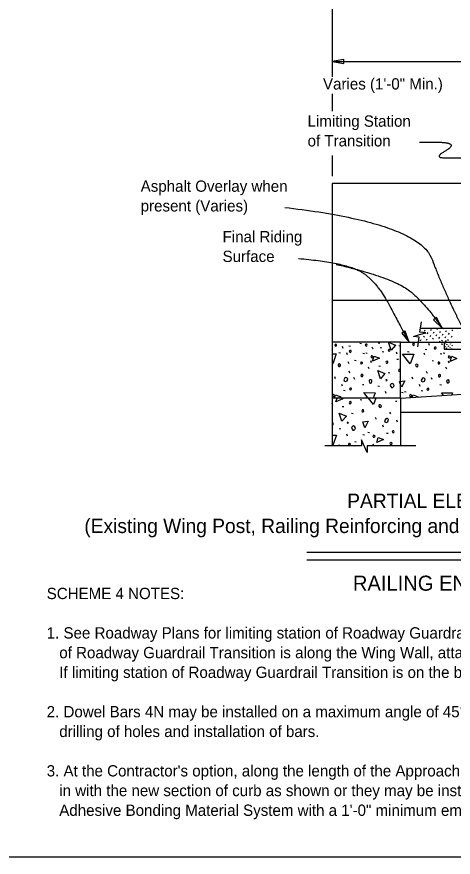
# Model space of a CAD drawing. Extents: x 1.5 to 68.7, y 0 to 31.1.
# Drawn here: x 20.65 to 28.44, y 1.78 to 16.79 of the extents above; entities that cross this region are included whole.
import ezdxf

# ---------------------------------------------------------------- set-up
doc = ezdxf.new("R2010")
doc.units = 0
for name, color, linetype in [('ActivePts-ConstElements', 7, 'Continuous'), ('AdhocPoint_dp', 7, 'Continuous'), ('Patterning', 7, 'Continuous'), ('PlotBorder_dp', 7, 'Continuous'), ('SheetBorder_dp', 7, 'Continuous')]:
    doc.layers.add(name, color=color, linetype=linetype)

msp = doc.modelspace()

# ---------------------------------------------------------------- linework, layer by layer
at = {"layer": 'ActivePts-ConstElements'}
msp.add_lwpolyline([(1.467, 28.183), (42.533, 28.183), (42.533, 1.783), (1.467, 1.783)], close=True, dxfattribs=at)
at = {"layer": 'AdhocPoint_dp'}
for p, q in [((26.277, 20.091), (26.277, 15.724)), ((26.277, 15.416), (26.277, 15.106)), ((26.277, 14.316), (26.277, 13.949)), ((30.085, 7.224), (25.826, 7.224)), ((30.085, 7.091), (25.826, 7.091))]:
    msp.add_line(p, q, dxfattribs=at)
for points in [[(26.277, 15.998), (26.485, 15.963), (26.485, 16.033)], [(28.238, 11.235), (28.141, 11.423), (28.085, 11.381)], [(27.652, 10.983), (27.579, 11.181), (27.518, 11.146)]]:
    msp.add_lwpolyline(points, close=True, dxfattribs=at)
for points in [[(26.277, 15.998), (29.811, 15.998)], [(27.809, 10.898), (27.832, 11.072), (27.73, 11.086), (27.838, 11.117), (27.947, 11.148), (27.844, 11.161), (27.869, 11.344)], [(27.77, 9.13), (26.901, 9.13), (26.901, 9.013), (26.802, 9.238), (26.802, 9.13), (26.146, 9.13)]]:
    msp.add_lwpolyline(points, dxfattribs=at)
for points in [[(27.836, 14.553), (28.073, 14.553), (28.329, 14.553), (28.447, 14.486), (28.102, 14.277), (28.44, 14.277), (28.701, 14.277)], [(25.434, 13.39), (27.814, 13.112), (28.299, 11.826), (28.608, 11.234)], [(25.677, 12.477), (26.504, 12.407), (27.069, 12.08), (27.575, 11.117), (27.652, 10.983)], [(26.348, 12.372), (27.415, 12.129), (28.009, 11.586), (28.238, 11.235)]]:
    msp.add_open_spline(points, degree=2, dxfattribs=at)
at = {"layer": 'Patterning'}
for p, q in [((27.878, 11.229), (27.881, 11.234)), ((27.927, 11.18), (27.94, 11.202)), ((27.975, 11.131), (27.988, 11.154)), ((28.037, 11.193), (28.05, 11.215)), ((28.086, 11.144), (28.099, 11.167)), ((28.135, 11.095), (28.148, 11.118)), ((28.148, 11.206), (28.161, 11.228)), ((28.197, 11.157), (28.21, 11.18)), ((28.245, 11.108), (28.258, 11.131)), ((28.258, 11.219), (28.267, 11.234)), ((28.307, 11.17), (28.32, 11.193)), ((28.356, 11.121), (28.369, 11.144)), ((28.369, 11.232), (28.371, 11.234)), ((28.418, 11.183), (28.431, 11.205)), ((26.77, 10.962), (26.8, 10.957)), ((27.099, 10.97), (27.129, 10.965)), ((27.812, 10.988), (27.825, 11.01)), ((27.852, 11.008), (27.865, 11.03)), ((27.914, 11.069), (27.927, 11.092)), ((27.962, 11.021), (27.975, 11.043)), ((28.024, 11.082), (28.037, 11.105)), ((28.073, 11.034), (28.086, 11.056)), ((28.184, 11.047), (28.197, 11.069)), ((28.194, 10.982), (28.205, 11)), ((28.233, 10.998), (28.245, 11.02)), ((28.294, 11.059), (28.307, 11.082)), ((28.298, 10.964), (28.306, 10.978)), ((28.303, 10.991), (28.316, 11.013)), ((28.343, 11.011), (28.356, 11.033)), ((28.361, 10.972), (28.368, 10.984)), ((28.399, 10.983), (28.4, 10.984)), ((28.405, 11.072), (28.418, 11.095)), ((28.425, 10.98), (28.427, 10.984)), ((26.474, 10.868), (26.46, 10.904)), ((26.574, 10.918), (26.604, 10.912)), ((27.007, 10.856), (26.993, 10.892)), ((27.135, 10.886), (27.165, 10.88)), ((27.171, 10.814), (27.201, 10.808)), ((27.467, 10.926), (27.497, 10.92)), ((27.619, 10.814), (27.649, 10.808)), ((27.94, 10.858), (27.97, 10.852)), ((28.016, 10.921), (28.002, 10.956)), ((28.224, 10.954), (28.254, 10.949)), ((28.289, 10.9), (28.298, 10.914)), ((28.317, 10.872), (28.325, 10.886)), ((28.325, 10.936), (28.333, 10.95)), ((28.353, 10.908), (28.361, 10.922)), ((28.381, 10.881), (28.389, 10.895)), ((28.389, 10.944), (28.397, 10.958)), ((28.412, 10.859), (28.416, 10.867)), ((28.416, 10.916), (28.425, 10.93)), ((26.398, 10.797), (26.428, 10.792)), ((26.549, 10.759), (26.537, 10.792)), ((26.677, 10.66), (26.703, 10.654)), ((26.823, 10.785), (26.852, 10.778)), ((26.875, 10.795), (26.903, 10.787)), ((27.439, 10.768), (27.425, 10.804)), ((27.434, 10.681), (27.461, 10.676)), ((27.933, 10.755), (27.92, 10.789)), ((28.207, 10.782), (28.235, 10.775)), ((28.258, 10.791), (28.287, 10.784)), ((26.578, 10.596), (26.564, 10.631)), ((26.939, 10.504), (26.925, 10.539)), ((26.981, 10.613), (26.969, 10.647)), ((27.111, 10.559), (27.142, 10.555)), ((28.06, 10.656), (28.086, 10.651)), ((28.322, 10.5), (28.308, 10.536)), ((28.364, 10.61), (28.352, 10.643)), ((26.337, 10.327), (26.323, 10.363)), ((26.594, 10.428), (26.579, 10.464)), ((27.279, 10.441), (27.307, 10.433)), ((27.72, 10.324), (27.706, 10.359)), ((27.977, 10.425), (27.963, 10.46)), ((26.463, 10.195), (26.45, 10.228)), ((26.681, 10.316), (26.666, 10.352)), ((26.818, 10.228), (26.843, 10.224)), ((27.846, 10.191), (27.834, 10.225)), ((28.064, 10.313), (28.05, 10.348)), ((28.202, 10.224), (28.227, 10.221)), ((26.481, 10.124), (26.511, 10.118)), ((27.094, 10.2), (27.124, 10.194)), ((27.243, 10.065), (27.23, 10.099)), ((27.517, 10.092), (27.545, 10.085)), ((27.568, 10.101), (27.597, 10.094)), ((27.864, 10.12), (27.894, 10.115)), ((26.744, 9.991), (26.771, 9.986)), ((26.744, 9.991), (26.771, 9.986)), ((26.779, 9.956), (26.806, 9.951)), ((27.405, 9.931), (27.431, 9.926)), ((26.291, 9.854), (26.279, 9.887)), ((26.456, 9.834), (26.487, 9.831)), ((26.624, 9.716), (26.652, 9.709)), ((27.066, 9.599), (27.051, 9.634)), ((27.322, 9.7), (27.308, 9.735)), ((27.191, 9.466), (27.179, 9.5)), ((27.444, 9.553), (27.43, 9.588)), ((26.404, 9.44), (26.434, 9.435)), ((26.553, 9.306), (26.54, 9.339)), ((26.827, 9.332), (26.855, 9.325)), ((26.913, 9.376), (26.942, 9.369)), ((27.244, 9.36), (27.274, 9.355)), ((26.68, 9.207), (26.707, 9.201)), ((27.018, 9.13), (27.007, 9.159))]:
    msp.add_line(p, q, dxfattribs=at)
for points in [[(27.33, 10.838), (27.282, 10.984), (27.408, 10.93), (27.33, 10.838)], [(27.719, 10.934), (27.729, 10.924), (27.74, 10.931), (27.747, 10.941), (27.743, 10.959), (27.735, 10.961), (27.722, 10.959), (27.712, 10.948), (27.719, 10.934)], [(26.329, 10.918), (26.34, 10.907), (26.35, 10.915), (26.357, 10.925), (26.354, 10.943), (26.345, 10.945), (26.332, 10.943), (26.322, 10.932), (26.329, 10.918)], [(26.589, 10.81), (26.6, 10.799), (26.61, 10.806), (26.618, 10.817), (26.614, 10.835), (26.605, 10.836), (26.593, 10.835), (26.582, 10.824), (26.589, 10.81)], [(26.874, 10.922), (26.884, 10.911), (26.895, 10.919), (26.902, 10.929), (26.898, 10.947), (26.889, 10.949), (26.877, 10.947), (26.867, 10.936), (26.874, 10.922)], [(27.282, 10.826), (27.293, 10.815), (27.303, 10.822), (27.31, 10.833), (27.307, 10.851), (27.298, 10.852), (27.286, 10.851), (27.275, 10.84), (27.282, 10.826)], [(28.103, 10.866), (28.114, 10.855), (28.124, 10.862), (28.131, 10.873), (28.128, 10.891), (28.119, 10.893), (28.107, 10.891), (28.096, 10.88), (28.103, 10.866)], [(26.277, 10.774), (26.351, 10.773), (26.286, 10.598)], [(26.978, 10.706), (26.99, 10.704), (27.002, 10.71), (27.006, 10.72), (27.001, 10.729), (26.99, 10.736), (26.978, 10.741), (26.971, 10.727), (26.967, 10.717), (26.978, 10.706)], [(26.999, 10.642), (27.028, 10.734), (27.121, 10.697), (26.999, 10.642)], [(27.669, 10.594), (27.535, 10.771), (27.735, 10.769), (27.669, 10.594)], [(28.361, 10.703), (28.373, 10.701), (28.386, 10.706), (28.389, 10.717), (28.384, 10.726), (28.373, 10.733), (28.361, 10.738), (28.354, 10.724), (28.35, 10.713), (28.361, 10.703)], [(28.383, 10.639), (28.411, 10.73), (28.505, 10.693), (28.383, 10.639)], [(26.286, 10.598), (26.277, 10.609)], [(26.385, 10.566), (26.394, 10.55), (26.415, 10.547), (26.424, 10.563), (26.427, 10.577), (26.419, 10.585), (26.403, 10.594), (26.387, 10.589), (26.381, 10.573), (26.385, 10.566)], [(26.784, 10.601), (26.804, 10.596), (26.816, 10.605), (26.818, 10.617), (26.815, 10.621), (26.8, 10.628), (26.788, 10.626), (26.786, 10.614), (26.784, 10.601)], [(27.247, 10.607), (27.254, 10.607), (27.268, 10.614), (27.273, 10.63), (27.271, 10.639), (27.257, 10.646), (27.24, 10.635), (27.236, 10.624), (27.24, 10.614), (27.247, 10.607)], [(27.768, 10.563), (27.777, 10.547), (27.798, 10.543), (27.807, 10.559), (27.811, 10.573), (27.802, 10.582), (27.786, 10.591), (27.77, 10.585), (27.765, 10.57), (27.768, 10.563)], [(28.168, 10.598), (28.187, 10.593), (28.2, 10.601), (28.201, 10.614), (28.198, 10.617), (28.184, 10.624), (28.171, 10.623), (28.17, 10.61), (28.168, 10.598)], [(26.79, 10.384), (26.799, 10.368), (26.818, 10.369), (26.827, 10.382), (26.829, 10.401), (26.817, 10.406), (26.808, 10.408), (26.797, 10.405), (26.794, 10.401), (26.79, 10.384)], [(27.142, 10.329), (27.094, 10.475), (27.22, 10.421), (27.142, 10.329)], [(27.466, 10.465), (27.487, 10.465), (27.498, 10.476), (27.492, 10.495), (27.469, 10.497), (27.466, 10.486), (27.461, 10.478), (27.466, 10.465), (27.462, 10.469)], [(28.173, 10.38), (28.182, 10.364), (28.202, 10.366), (28.211, 10.378), (28.212, 10.398), (28.2, 10.403), (28.191, 10.405), (28.181, 10.401), (28.177, 10.398), (28.173, 10.38)], [(26.491, 10.29), (26.514, 10.278), (26.544, 10.29), (26.556, 10.327), (26.539, 10.345), (26.516, 10.35), (26.505, 10.343), (26.493, 10.324), (26.484, 10.308), (26.491, 10.29)], [(26.935, 10.285), (26.946, 10.263), (26.963, 10.253), (26.978, 10.263), (26.985, 10.274), (26.985, 10.295), (26.969, 10.311), (26.949, 10.309), (26.94, 10.3), (26.935, 10.285)], [(27.241, 10.293), (27.26, 10.302), (27.253, 10.309), (27.241, 10.315), (27.236, 10.302), (27.241, 10.293)], [(27.312, 10.209), (27.335, 10.171), (27.358, 10.173), (27.367, 10.182), (27.386, 10.201), (27.374, 10.231), (27.349, 10.246), (27.331, 10.239), (27.317, 10.224), (27.312, 10.209)], [(27.514, 10.177), (27.48, 10.281), (27.574, 10.294), (27.514, 10.177)], [(27.874, 10.287), (27.897, 10.274), (27.927, 10.287), (27.94, 10.324), (27.922, 10.342), (27.899, 10.347), (27.888, 10.34), (27.876, 10.32), (27.867, 10.304), (27.874, 10.287)], [(28.318, 10.281), (28.329, 10.26), (28.347, 10.249), (28.361, 10.26), (28.368, 10.27), (28.368, 10.292), (28.352, 10.308), (28.333, 10.306), (28.324, 10.297), (28.318, 10.281)], [(26.592, 10.136), (26.603, 10.125), (26.613, 10.132), (26.621, 10.143), (26.617, 10.161), (26.608, 10.163), (26.596, 10.161), (26.585, 10.15), (26.592, 10.136)], [(26.919, 9.984), (26.845, 10.081), (27.045, 10.079), (27.009, 9.984)], [(27.975, 10.132), (27.986, 10.122), (27.997, 10.129), (28.004, 10.14), (28, 10.157), (27.991, 10.159), (27.979, 10.157), (27.968, 10.147), (27.975, 10.132)], [(28.263, 10.032), (28.228, 10.078), (28.428, 10.076), (28.415, 10.042)], [(26.288, 10.016), (26.3, 10.014), (26.312, 10.02), (26.316, 10.03), (26.311, 10.039), (26.3, 10.046), (26.288, 10.052), (26.281, 10.037), (26.277, 10.027)], [(26.277, 10.027), (26.288, 10.016)], [(26.319, 9.984), (26.338, 10.044), (26.431, 10.007), (26.381, 9.984)], [(26.344, 9.917), (26.365, 9.984)], [(26.435, 9.984), (26.466, 9.972), (26.344, 9.917)], [(26.592, 9.882), (26.599, 9.882), (26.613, 9.889), (26.618, 9.905), (26.616, 9.914), (26.602, 9.921), (26.585, 9.91), (26.581, 9.9), (26.585, 9.889), (26.592, 9.882)], [(27.014, 9.87), (26.927, 9.984)], [(27.057, 9.984), (27.014, 9.87)], [(27.671, 10.013), (27.683, 10.011), (27.696, 10.016), (27.699, 10.027), (27.694, 10.036), (27.683, 10.043), (27.671, 10.048), (27.664, 10.034), (27.66, 10.023), (27.671, 10.013)], [(27.708, 9.998), (27.721, 10.041), (27.813, 10.004)], [(26.811, 9.74), (26.832, 9.74), (26.843, 9.751), (26.837, 9.771), (26.814, 9.772), (26.811, 9.762), (26.806, 9.753), (26.811, 9.74), (26.807, 9.744)], [(27.113, 9.838), (27.122, 9.822), (27.143, 9.818), (27.152, 9.834), (27.156, 9.848), (27.147, 9.857), (27.131, 9.866), (27.115, 9.861), (27.11, 9.845), (27.113, 9.838)], [(26.452, 9.569), (26.404, 9.716), (26.53, 9.661), (26.452, 9.569)], [(27.219, 9.562), (27.242, 9.55), (27.272, 9.562), (27.285, 9.599), (27.267, 9.617), (27.244, 9.622), (27.233, 9.615), (27.221, 9.596), (27.212, 9.58), (27.219, 9.562)], [(26.277, 9.496), (26.288, 9.504), (26.295, 9.514), (26.295, 9.535), (26.279, 9.551), (26.277, 9.551)], [(26.551, 9.534), (26.571, 9.543), (26.563, 9.55), (26.551, 9.555), (26.546, 9.543), (26.551, 9.534)], [(26.622, 9.449), (26.645, 9.412), (26.668, 9.413), (26.677, 9.422), (26.696, 9.442), (26.684, 9.472), (26.659, 9.486), (26.641, 9.479), (26.627, 9.465), (26.622, 9.449)], [(26.859, 9.452), (26.825, 9.557), (26.919, 9.569), (26.859, 9.452)], [(26.277, 9.32), (26.355, 9.32), (26.289, 9.145)], [(27.016, 9.288), (27.028, 9.286), (27.041, 9.291), (27.044, 9.302), (27.039, 9.311), (27.028, 9.318), (27.016, 9.323), (27.009, 9.309), (27.005, 9.299), (27.016, 9.288)], [(27.355, 9.373), (27.366, 9.362), (27.377, 9.369), (27.384, 9.38), (27.38, 9.398), (27.371, 9.399), (27.359, 9.398), (27.348, 9.387), (27.355, 9.373)], [(26.289, 9.145), (26.277, 9.161)], [(26.569, 9.148), (26.588, 9.143), (26.601, 9.152), (26.603, 9.164), (26.599, 9.168), (26.585, 9.175), (26.572, 9.173), (26.571, 9.161), (26.569, 9.148)], [(27.073, 9.189), (27.101, 9.281), (27.195, 9.244), (27.073, 9.189)], [(27.32, 9.154), (27.327, 9.154), (27.341, 9.161), (27.347, 9.177), (27.345, 9.185), (27.331, 9.192), (27.313, 9.182), (27.309, 9.171), (27.313, 9.161), (27.32, 9.154)], [(26.425, 9.13), (26.422, 9.132), (26.406, 9.141), (26.39, 9.136), (26.388, 9.13)]]:
    msp.add_lwpolyline(points, dxfattribs=at)
at = {"layer": 'PlotBorder_dp'}
for p, q in [((26.277, 13.818), (26.277, 11.734)), ((36.552, 13.818), (26.277, 13.818)), ((26.277, 11.734), (36.676, 11.734)), ((26.277, 11.734), (26.277, 10.984)), ((27.854, 11.234), (30.116, 11.234)), ((26.277, 10.984), (26.277, 9.13)), ((27.497, 10.984), (26.277, 10.984)), ((27.497, 10.003), (27.497, 10.984)), ((27.497, 10.984), (37.698, 10.984)), ((28.277, 10.984), (28.277, 10.859)), ((28.277, 10.859), (34.222, 10.859)), ((27.497, 9.984), (31.497, 10.234)), ((27.497, 9.984), (26.277, 9.984)), ((27.497, 9.984), (27.497, 9.13)), ((27.497, 9.984), (27.497, 9.13)), ((27.497, 9.984), (27.497, 9.734)), ((27.497, 9.734), (36.676, 9.734))]:
    msp.add_line(p, q, dxfattribs=at)

# ---------------------------------------------------------------- texts
at = {"layer": 'AdhocPoint_dp'}
for s, height, p in [('Limiting Station ', 0.2016, (25.838, 14.831)), ('of Transition', 0.2016, (25.838, 14.479)), ('Asphalt Overlay when ', 0.2016, (22.858, 13.669)), ('present (Varies)', 0.2016, (22.858, 13.317)), ('Final Riding ', 0.2016, (24.32, 12.767)), ('Surface', 0.2016, (24.32, 12.415)), ('PARTIAL ELEVATION OF INSIDE FACE OF RAILING', 0.256, (26.546, 8.021)), ('(Existing Wing Post, Railing Reinforcing and Expansion Dowel Assemblies not shown for clarity)', 0.256, (21.852, 7.573)), ('RAILING END TREATMENT FOR FLARED CURBS', 0.2688, (26.647, 6.543)), ('SCHEME 4 NOTES:', 0.2016, (21.18, 6.393)), ('1. See Roadway Plans for limiting station of Roadway Guardrail Transition or other site specific treatment.  If limiting station ', 0.2016, (21.18, 5.689)), ('   of Roadway Guardrail Transition is along the Wing Wall, attach Thrie-Beam Terminal Connector to railing as shown above.  ', 0.2016, (21.18, 5.337)), ('   If limiting station of Roadway Guardrail Transition is on the bridge, see Sheet 3 of 6.', 0.2016, (21.18, 4.985)), ('2. Dowel Bars 4N may be installed on a maximum angle of 45° to the cut edge of the Approach Slab as shown to facilitate ', 0.2016, (21.18, 4.281)), ('   drilling of holes and installation of bars.', 0.2016, (21.18, 3.929)), ("3. At the Contractor's option, along the length of the Approach Slab curb that is to be replaced, Dowel Bars 6D may be cast ", 0.2016, (21.18, 3.225)), ('   in with the new section of curb as shown or they may be installed in drilled holes in the new section of curb using an ', 0.2016, (21.18, 2.873)), ('   Adhesive Bonding Material System with a 1\'-0" minimum embedment. ', 0.2016, (21.18, 2.521))]:
    msp.add_text(s, height=height, dxfattribs=at).set_placement(p)
at = {"layer": 'SheetBorder_dp'}
msp.add_text('Varies (1\'-0" Min.)', height=0.2016, dxfattribs=at).set_placement((26.113, 15.496))

doc.saveas('drawing.dxf')
